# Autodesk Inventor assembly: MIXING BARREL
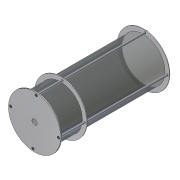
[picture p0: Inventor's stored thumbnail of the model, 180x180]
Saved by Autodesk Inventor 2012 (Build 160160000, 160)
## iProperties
Created: 2011-05
Part Number: MIXING BARREL
Document SubType Name: Assembly
Designer: Dimitris
Author: Dimitris
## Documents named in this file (9)
- K:\Autodesk CMU Course\Week 5 - Inventor Design Automation\Projects\Files\iLogic\MIXING BARREL.iam
- K:\Autodesk CMU Course\Week 5 - Inventor Design Automation\Projects\Files\iLogic\Parts\PERFORATED METAL SHEET.ipt
- K:\Autodesk CMU Course\Week 5 - Inventor Design Automation\Projects\Files\iLogic\Parts\OUTSIDE FLANGE RING.ipt
- K:\Autodesk CMU Course\Week 5 - Inventor Design Automation\Projects\Files\iLogic\Parts\INSIDE FLANGE RING.ipt
- K:\Autodesk CMU Course\Week 5 - Inventor Design Automation\Projects\Files\iLogic\Parts\OUTSIDE ROD.ipt
- K:\Autodesk CMU Course\Week 5 - Inventor Design Automation\Projects\Files\iLogic\Parts\BLIND FLANGE.ipt
- K:\Autodesk CMU Course\Week 5 - Inventor Design Automation\Projects\Files\iLogic\Libraries\Content Center Files\R2012\en-US\ASME ANSI B18.3.5M(2)\ASME_ANSI B18.3.5M - M10x16(2).ipt
- K:\Autodesk CMU Course\Week 5 - Inventor Design Automation\Projects\Files\iLogic\Libraries\Content Center Files\R2012\en-US\IFI 542(1)\IFI 542 - 12(1).ipt
- K:\Autodesk CMU Course\Week 5 - Inventor Design Automation\Projects\Files\iLogic\Libraries\Content Center Files\R2012\en-US\ANSI B18.3.1M(1)\ANSI B18.3.1M - M10x1.5 x 20(2).ipt
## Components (21 placed, 8 different names)
1. PERFORATED METAL SHEET:1 — Insert:1, Insert:2, Insert:3
2. OUTSIDE FLANGE RING:1 — Insert:1, Insert:6, Insert:10
3. OUTSIDE FLANGE RING:2 — Insert:2, Mate:4
4. INSIDE FLANGE RING:1 — Insert:3, Mate:3
5. BLIND FLANGE:1 — Insert:10, Mate:2
6. OUTSIDE ROD:1 — Insert:6, Mate:2, Mate:3, Mate:4
7. Broached Hexagon Socket Flat Countersunk Head Cap Screws - Metric M10x16:1
8. Circular Washer (Metric) (IFI) 12:1
9. Broached Socket Head Cap Screw - Metric M10x1.5 x 20:1
10. OUTSIDE ROD:2
11. Broached Hexagon Socket Flat Countersunk Head Cap Screws - Metric M10x16:2
12. Circular Washer (Metric) (IFI) 12:2
13. Broached Socket Head Cap Screw - Metric M10x1.5 x 20:2
14. OUTSIDE ROD:3
15. Broached Hexagon Socket Flat Countersunk Head Cap Screws - Metric M10x16:3
16. Circular Washer (Metric) (IFI) 12:3
17. Broached Socket Head Cap Screw - Metric M10x1.5 x 20:3
18. OUTSIDE ROD:4
19. Broached Hexagon Socket Flat Countersunk Head Cap Screws - Metric M10x16:4
20. Circular Washer (Metric) (IFI) 12:4
21. Broached Socket Head Cap Screw - Metric M10x1.5 x 20:4
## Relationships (8: Insert 5, Mate 3)
- Insert:1: PERFORATED METAL SHEET:1 ↔ OUTSIDE FLANGE RING:1
- Insert:2: PERFORATED METAL SHEET:1 ↔ OUTSIDE FLANGE RING:2
- Insert:3: PERFORATED METAL SHEET:1 ↔ INSIDE FLANGE RING:1
- Insert:6: OUTSIDE FLANGE RING:1 ↔ OUTSIDE ROD:1
- Insert:10: OUTSIDE FLANGE RING:1 ↔ BLIND FLANGE:1
- Mate:2: BLIND FLANGE:1 ↔ OUTSIDE ROD:1
- Mate:3: INSIDE FLANGE RING:1 ↔ OUTSIDE ROD:1
- Mate:4: OUTSIDE FLANGE RING:2 ↔ OUTSIDE ROD:1
